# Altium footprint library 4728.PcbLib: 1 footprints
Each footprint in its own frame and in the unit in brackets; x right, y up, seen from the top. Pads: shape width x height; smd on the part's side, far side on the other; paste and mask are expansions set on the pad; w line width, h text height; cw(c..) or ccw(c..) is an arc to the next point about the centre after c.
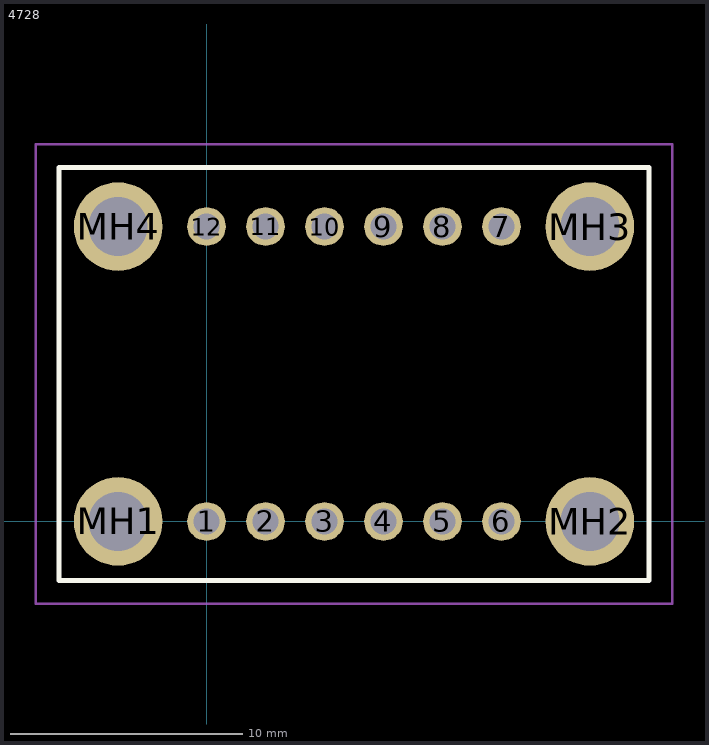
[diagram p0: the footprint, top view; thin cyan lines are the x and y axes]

## 4728 [mm]
pads (16):
  round 1.665 hole 1.11: 1(0,0) 2(2.54,0) 3(5.08,0) 4(7.62,0) 5(10.16,0) 6(12.7,0) 7(12.7,12.7) 8(10.16,12.7) 9(7.62,12.7) 10(5.08,12.7) 11(2.54,12.7) 12(0,12.7)
  round 3.81 hole 2.54: MH1(-3.81,0) MH2(16.51,0) MH3(16.51,12.7) MH4(-3.81,12.7)
Top Overlay:
  lines w0.2: -6.35,-2.54 19.05,-2.54 19.05,15.24 -6.35,15.24 -6.35,-2.54
Mechanical 15:
  lines w0.1: -6.35,-2.54 19.05,-2.54 19.05,15.24 -6.35,15.24 -6.35,-2.54
Mechanical 20:
  lines w0.1: -7.35,-3.54 20.05,-3.54 20.05,16.24 -7.35,16.24 -7.35,-3.54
